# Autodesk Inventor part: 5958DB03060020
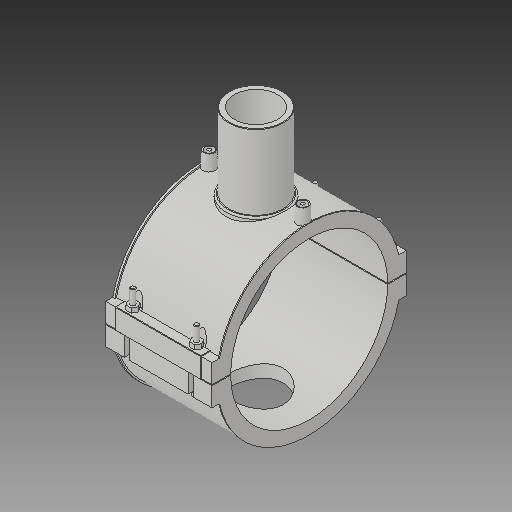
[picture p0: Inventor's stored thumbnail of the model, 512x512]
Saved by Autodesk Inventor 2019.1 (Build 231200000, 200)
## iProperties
Created: 2017-07
Part Number: 5958DB03060020
Material: Generic
Description: PLASSON BRANCH SADDLE 6''DIPS x 2''IPS
Document SubType Name: Modeling
Designer: KIM
Mass: 764.267 g
Surface Area: 1930.38 cm^2
Volume: 764.267 cm^3
Density: 1 g/cm^3
Appearance: Default
Author: KIM
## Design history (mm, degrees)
derived "5958D (1).ipt"
feature "Solid6::5958D (1).ipt"
feature "Solid7::5958D (1).ipt"
feature "Solid8::5958D (1).ipt"
tag "TaggingFeature1"
body "Solid1"
body "Solid2"
body "Solid3"
other parameters: "d_" = 174.5, "d1" = 60.1, "B_" = 215.9, "H_" = 97.028, "H1" = 83.566, "L" = 118.11, "t" = 6, "d244" = 174.5, "d245" = 13.462, "d246" = 43.625, "d247" = 43.625, "d248" = 215.9, "d249" = 107.95, "d250" = 1, "d252" = 87.25, "d253" = 87.25, "d254" = 13.462, "d255" = 13.462, "d256" = 215.9, "d257" = 21.8125, "d258" = 107.95, "d259" = 0.5, "d260" = 118.11, "d261" = 0, "d262" = 70.866, "d263" = 6, "d271" = 0, "d272" = 3, "d274" = 3, "d277" = 3, "d278" = 3, "d279" = 5.4, "d280" = 0, "d281" = 0, "d283" = 43.625, "d284" = 0.6, "d287" = 101.25048, "d288" = 66.11, "d290" = 0, "d291" = 184.278, "d292" = 60.1, "d294" = 0, "d295" = 3, "d296" = 15, "d297" = 15, "d298" = 25.4, "d299" = 0, "d300" = 1, "d302" = 94.488, "d303" = 0, "d306" = 5, "d307" = 0, "d308" = 1, "d309" = 117.25, "d310" = 12, "d311" = 12, "d315" = 3 deg, "d316" = 4, "d318" = 4, "d320" = 14, "d321" = 0, "d322" = 0.5, "d323" = 1.745, "d324" = 1.745, "d325" = 2.3622, "d326" = 0, "d327" = 1.1811, "d328" = 1.1811, "d329" = 1.1811, "d330" = 0, "d331" = 1.803, "d332" = 48.08, "d334" = 0, "d336" = 0, "d337" = 0.601, "d340" = 7.0866, "d341" = 7.0866
